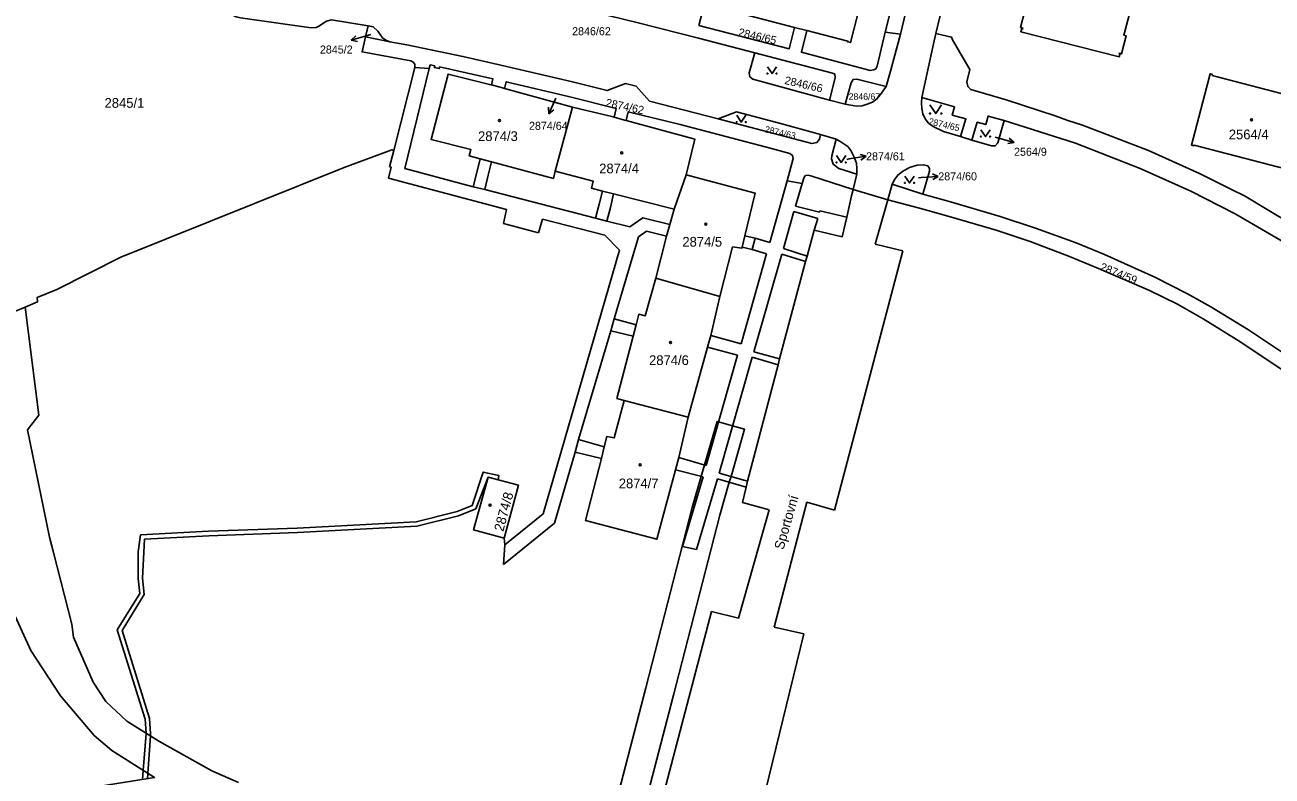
# Model space of a CAD drawing. Extents: x -869103 to -863415, y -1015889 to -1012477.
# Drawn here: x -866820.8 to -866602.7, y -1014847 to -1014715.6 of the extents above; entities that cross this region are included whole.
import ezdxf

# ---------------------------------------------------------------- set-up
doc = ezdxf.new("R2010")
doc.units = 0
for name, color, linetype in [('Hranice parcel', 7, 'Continuous'), ('Parcelní čísla', 7, 'Continuous'), ('Pop  PČ popisy', 7, 'Continuous'), ('Vnitřní kresba', 7, 'Continuous'), ('Věcná břemena k části', 7, 'Continuous'), ('Značky budov', 7, 'Continuous'), ('Značky kultur', 7, 'Continuous')]:
    doc.layers.add(name, color=color, linetype=linetype)

msp = doc.modelspace()

# ---------------------------------------------------------------- linework, layer by layer
at = {"layer": 'Hranice parcel'}
for p, q in [((-866694.25, -1014713.99), (-866686.19, -1014716.05)), ((-866660.75, -1014713.97), (-866661.48, -1014717.12)), ((-866761.23, -1014717.72), (-866760.79, -1014715.79)), ((-866686.19, -1014716.05), (-866684.08, -1014716.59)), ((-866756.99, -1014718.55), (-866761.23, -1014717.72)), ((-866725.06, -1014730), (-866736.96, -1014726.73)), ((-866728.05, -1014741.2), (-866725.06, -1014730)), ((-866677.35, -1014729.5), (-866680.09, -1014728.77)), ((-866681.65, -1014734.8), (-866678.94, -1014735.59)), ((-866655.18, -1014735.77), (-866657.2, -1014735.13)), ((-866707.28, -1014747.85), (-866705.19, -1014741.82)), ((-866675.33, -1014741.7), (-866675.98, -1014744.38)), ((-866675.98, -1014744.38), (-866669.88, -1014746.2)), ((-866669.88, -1014746.2), (-866669.11, -1014743.46)), ((-866663.75, -1014745.2), (-866669.11, -1014743.46)), ((-866710.47, -1014759.93), (-866699.29, -1014763.09)), ((-866716.01, -1014781.3), (-866704.79, -1014784.2))]:
    msp.add_line(p, q, dxfattribs=at)
for points in [[(-866676.2, -1014693.64), (-866667.77, -1014702.31), (-866665.84, -1014706.34), (-866665.79, -1014709.38), (-866667.66, -1014717.25)], [(-866691.76, -1014702.91), (-866691.38, -1014701.47), (-866691, -1014701.57), (-866691.05, -1014701.76), (-866684.3, -1014703.53), (-866682.18, -1014704.08), (-866673.55, -1014706.33), (-866673.5, -1014706.14), (-866673.21, -1014706.17), (-866676.42, -1014718.71), (-866676.9, -1014718.59), (-866676.86, -1014718.44), (-866684.08, -1014716.59)], [(-866693.17, -1014720.49), (-866702.98, -1014717.94), (-866713.55, -1014715.25), (-866726.44, -1014712.08), (-866735.83, -1014709.92), (-866754.2, -1014705.82), (-866768.07, -1014703.14), (-866768.98, -1014707.12), (-866769.32, -1014707.68), (-866769.96, -1014707.85)], [(-866835.15, -1014723.88), (-866828.17, -1014723.42), (-866829.04, -1014715.45), (-866829.11, -1014714.03), (-866828.96, -1014712.67), (-866828.33, -1014711.34), (-866827.39, -1014710.28), (-866826.14, -1014709.44), (-866824.74, -1014708.9), (-866823.27, -1014708.71), (-866814.43, -1014709.34), (-866801.35, -1014710.35), (-866794.57, -1014711), (-866787.9, -1014711.79), (-866784.54, -1014713.88), (-866783.84, -1014714.23), (-866783.1, -1014714.4), (-866770.74, -1014716.15), (-866769.87, -1014716.09), (-866769.4, -1014715.86), (-866768.07, -1014714.98), (-866767.19, -1014714.73), (-866760.79, -1014715.79)], [(-866645.9, -1014712.93), (-866646.71, -1014716.08), (-866646.31, -1014716.17), (-866646.33, -1014716.34), (-866646.48, -1014716.31), (-866646.64, -1014716.81), (-866629.43, -1014721.18), (-866629.3, -1014720.8), (-866629.43, -1014720.75), (-866629.4, -1014720.57), (-866629.03, -1014720.68), (-866628.19, -1014717.5), (-866628.59, -1014717.41), (-866626.69, -1014710.13)], [(-866686.19, -1014716.05), (-866687.16, -1014719.83), (-866702.93, -1014715.72), (-866702.32, -1014713.29)], [(-866760.79, -1014715.79), (-866759.9, -1014715.95), (-866759.11, -1014716.7), (-866758.25, -1014717.89), (-866757.69, -1014718.29), (-866756.99, -1014718.55)], [(-866684.08, -1014716.59), (-866685.01, -1014720.39), (-866672.99, -1014723.57), (-866672.33, -1014723.5), (-866671.97, -1014723.28), (-866671.76, -1014722.83), (-866670.36, -1014716.88), (-866667.66, -1014717.25)], [(-866752.64, -1014723.04), (-866752.62, -1014722.46), (-866752.89, -1014722.13), (-866753.32, -1014721.92), (-866761.83, -1014720.35), (-866761.23, -1014717.72)], [(-866756.99, -1014718.55), (-866754.03, -1014719.11), (-866744.2, -1014721.14), (-866737.58, -1014722.63), (-866725.03, -1014725.6), (-866719, -1014727.11), (-866715.8, -1014725.87), (-866713.9, -1014726.33), (-866711.56, -1014728.97), (-866699.58, -1014732.03)], [(-866667.66, -1014717.25), (-866669.43, -1014723.71), (-866670.21, -1014726.36)], [(-866663.95, -1014728.29), (-866661.9, -1014718.91), (-866661.48, -1014717.12)], [(-866661.48, -1014717.12), (-866658.73, -1014717.76), (-866658.61, -1014718.22), (-866655.54, -1014723.43), (-866656.06, -1014725.6), (-866655.92, -1014726.41), (-866655.35, -1014726.9), (-866649.22, -1014728.72), (-866640.65, -1014731.52), (-866638.41, -1014732.31), (-866635.84, -1014733.17), (-866624.3, -1014737.59), (-866615.38, -1014741.59), (-866609.67, -1014744.44), (-866607.53, -1014745.53), (-866598.99, -1014750.64)], [(-866680.09, -1014728.77), (-866693.48, -1014725.1), (-866694.03, -1014724.68), (-866694.12, -1014724.02), (-866693.17, -1014720.49)], [(-866693.17, -1014720.49), (-866679.57, -1014724.06), (-866679.14, -1014724.24), (-866679.08, -1014724.89), (-866680.09, -1014728.77)], [(-866752.64, -1014723.04), (-866756.29, -1014737.57), (-866756.65, -1014737.49), (-866764.99, -1014740.53), (-866804.04, -1014756.24), (-866815.22, -1014761.87), (-866818.64, -1014763.28), (-866818.58, -1014764.06), (-866820.77, -1014764.96), (-866834.88, -1014770.72)], [(-866739.23, -1014726.12), (-866738.96, -1014725.03), (-866748.29, -1014722.96), (-866748.35, -1014723.26), (-866749.18, -1014723.08), (-866749.12, -1014722.78), (-866749.92, -1014722.6), (-866750.11, -1014723.23), (-866752.64, -1014723.04)], [(-866728.05, -1014741.2), (-866728.38, -1014742.46), (-866739.21, -1014739.58), (-866739.78, -1014741.91), (-866740.39, -1014744.39), (-866742.42, -1014743.91), (-866741.8, -1014741.4), (-866741.18, -1014739.05), (-866743.1, -1014738.54), (-866742.8, -1014737.43), (-866749.76, -1014735.65), (-866746.79, -1014724.26), (-866739.34, -1014726.09), (-866739.23, -1014726.12)], [(-866736.96, -1014726.73), (-866736.64, -1014725.56), (-866725.52, -1014728.21), (-866717.39, -1014730.26), (-866717.78, -1014731.75)], [(-866677.35, -1014729.5), (-866676.3, -1014725.72), (-866675.94, -1014725.14), (-866675.3, -1014725.1), (-866670.21, -1014726.36)], [(-866596, -1014731.53), (-866595.3, -1014728.92), (-866595.69, -1014728.82), (-866595.74, -1014728.99), (-866613.16, -1014724.44), (-866613.12, -1014724.27), (-866613.5, -1014724.16), (-866616.76, -1014736.66), (-866616.37, -1014736.76), (-866616.34, -1014736.64), (-866598.83, -1014741.19), (-866599.21, -1014742.64), (-866598.82, -1014742.75)], [(-866736.96, -1014726.73), (-866737.29, -1014726.64), (-866739.23, -1014726.12)], [(-866670.21, -1014726.36), (-866671.18, -1014727.81), (-866671.82, -1014728.54), (-866672.6, -1014729.1), (-866673.48, -1014729.49), (-866674.41, -1014729.76), (-866675.39, -1014729.81), (-866677.35, -1014729.5)], [(-866717.78, -1014731.75), (-866717.94, -1014731.71), (-866725.06, -1014730)], [(-866657.2, -1014735.13), (-866660.18, -1014734.23), (-866661.98, -1014733.4), (-866662.76, -1014732.78), (-866663.35, -1014732.03), (-866663.77, -1014731.18), (-866663.97, -1014730.25), (-866664.03, -1014729.27), (-866663.95, -1014728.29)], [(-866657.2, -1014735.13), (-866656.25, -1014732.07), (-866658.63, -1014731.41), (-866658.21, -1014729.94), (-866663.95, -1014728.29)], [(-866715.68, -1014732.34), (-866715.94, -1014732.27), (-866717.78, -1014731.75)], [(-866675.98, -1014744.38), (-866683.36, -1014742), (-866683.85, -1014741.89), (-866684.28, -1014741.94), (-866684.55, -1014742.23), (-866684.9, -1014743.32), (-866687.52, -1014742.86), (-866686.45, -1014738.99), (-866686.54, -1014738.44), (-866687.05, -1014738.11), (-866690.24, -1014737.24), (-866706.19, -1014733.06), (-866715.3, -1014730.79), (-866715.68, -1014732.34)], [(-866715.68, -1014732.34), (-866703.66, -1014735.58), (-866705.19, -1014741.82)], [(-866699.58, -1014732.03), (-866696.37, -1014730.83), (-866688.46, -1014732.93), (-866681.65, -1014734.8)], [(-866681.65, -1014734.8), (-866681.84, -1014735.57), (-866682.29, -1014736.2), (-866683.17, -1014736.33), (-866699.58, -1014732.03)], [(-866655.18, -1014735.77), (-866654.24, -1014732.65), (-866652.76, -1014733.04), (-866652.33, -1014731.57), (-866649.56, -1014732.34)], [(-866649.56, -1014732.34), (-866650.65, -1014736.26), (-866651.11, -1014736.76), (-866651.78, -1014736.78), (-866655.18, -1014735.77)], [(-866546.5, -1014803.41), (-866554.27, -1014793.99), (-866562.05, -1014784.82), (-866564.23, -1014782.48), (-866568.35, -1014778.52), (-866571.09, -1014776.01), (-866573.79, -1014779.12), (-866574.41, -1014779.47), (-866575.01, -1014779.24), (-866580.33, -1014774.69), (-866580.61, -1014774.09), (-866580.38, -1014773.5), (-866577.64, -1014770.29), (-866582.87, -1014765.85), (-866588.58, -1014761.57), (-866600.64, -1014753.58), (-866609.13, -1014748.63), (-866616.88, -1014744.71), (-866625.78, -1014740.71), (-866637.08, -1014736.32), (-866649.56, -1014732.34)], [(-866678.94, -1014735.59), (-866679.68, -1014738.49), (-866679.74, -1014739.03), (-866679.43, -1014739.97), (-866678.45, -1014740.7), (-866675.33, -1014741.7)], [(-866678.94, -1014735.59), (-866678.11, -1014736.05), (-866676.9, -1014736.89), (-866676.38, -1014737.59), (-866675.78, -1014738.73), (-866675.4, -1014739.81), (-866675.31, -1014740.73), (-866675.33, -1014741.7)], [(-866669.11, -1014743.46), (-866668.69, -1014742.61), (-866668.15, -1014741.87), (-866667.35, -1014741.25), (-866666.08, -1014740.53), (-866664.78, -1014740.12), (-866663.66, -1014740.1), (-866662.92, -1014740.26), (-866662.59, -1014740.74), (-866662.6, -1014741.19), (-866663.75, -1014745.2)], [(-866707.28, -1014747.85), (-866717.85, -1014745.17), (-866718.38, -1014747.53), (-866719.03, -1014749.94), (-866721.04, -1014749.42), (-866720.39, -1014746.98), (-866719.78, -1014744.68), (-866721.7, -1014744.19), (-866721.44, -1014742.92), (-866728.05, -1014741.2)], [(-866699.29, -1014763.09), (-866697.04, -1014754.43), (-866695.41, -1014754.64), (-866695.37, -1014754.47), (-866693.64, -1014754.91), (-866693.1, -1014752.91), (-866694.88, -1014752.48), (-866693.11, -1014745.01), (-866705.19, -1014741.82)], [(-866663.75, -1014745.2), (-866658.92, -1014746.54), (-866650.22, -1014749.09), (-866644.04, -1014751.13), (-866636.97, -1014753.7), (-866632.02, -1014755.75), (-866623.19, -1014759.72), (-866617.46, -1014762.63), (-866613.41, -1014764.9), (-866606.83, -1014768.94), (-866597.92, -1014774.88), (-866593.48, -1014778.27), (-866588.3, -1014782.62), (-866582.52, -1014787.83)], [(-866591.83, -1014783.07), (-866595.12, -1014780.28), (-866599.53, -1014776.88), (-866608.18, -1014771.11), (-866614.72, -1014767.04), (-866619.23, -1014764.46), (-866624.25, -1014762.01), (-866633.06, -1014758.21), (-866638.12, -1014756.14), (-866644.98, -1014753.48), (-866650.96, -1014751.53), (-866659.56, -1014748.99), (-866664.37, -1014747.65), (-866669.88, -1014746.2)], [(-866707.28, -1014747.85), (-866708.03, -1014750.49), (-866708.6, -1014752.57), (-866710.47, -1014759.93)], [(-866710.47, -1014759.93), (-866712.33, -1014766.5), (-866713.44, -1014766.21), (-866713.93, -1014768.08), (-866717.77, -1014767.03), (-866718.34, -1014769.09), (-866714.44, -1014770.07), (-866717.27, -1014780.97), (-866716.01, -1014781.3)], [(-866704.79, -1014784.2), (-866701.41, -1014771.94), (-866700.87, -1014769.9), (-866699.29, -1014763.09)], [(-866716.01, -1014781.3), (-866717.75, -1014787.83), (-866719.01, -1014787.57), (-866719.48, -1014789.42), (-866723.97, -1014788.12), (-866724.58, -1014790.31), (-866719.99, -1014791.42), (-866722.77, -1014802.26), (-866710.32, -1014805.54), (-866707.02, -1014793.39), (-866706.45, -1014791.28), (-866704.79, -1014784.2)], [(-866734.49, -1014796.11), (-866739.79, -1014794.67), (-866742.33, -1014803.92), (-866736.97, -1014805.36), (-866734.49, -1014796.11)], [(-866827.25, -1014800.81), (-866825.72, -1014805.55), (-866824.43, -1014811.6), (-866822.5, -1014818.99), (-866819.79, -1014824.98), (-866814.59, -1014832.94), (-866808.7, -1014839.84), (-866805.6, -1014842.52), (-866798.13, -1014847.24), (-866829.6, -1014852.2), (-866835.48, -1014853.5), (-866883.36, -1014859.32), (-866885.48, -1014836.57)]]:
    msp.add_lwpolyline(points, dxfattribs=at)
at = {"layer": 'Pop  PČ popisy'}
for p, q in [((-866760.89, -1014717.48), (-866763.78, -1014718.31)), ((-866763.78, -1014718.31), (-866762.95, -1014717.55)), ((-866763.78, -1014718.31), (-866762.67, -1014718.51)), ((-866760.34, -1014717.32), (-866760.89, -1014717.48)), ((-866729.16, -1014731.15), (-866729.21, -1014730.03)), ((-866727.94, -1014728.41), (-866729.16, -1014731.15)), ((-866729.16, -1014731.15), (-866728.3, -1014730.44)), ((-866651.14, -1014735.26), (-866650.71, -1014735.38)), ((-866650.71, -1014735.38), (-866647.81, -1014736.16)), ((-866647.81, -1014736.16), (-866648.91, -1014736.38)), ((-866647.81, -1014736.16), (-866648.65, -1014735.41)), ((-866676.66, -1014739.06), (-866673.7, -1014738.59)), ((-866673.7, -1014738.59), (-866674.76, -1014738.25)), ((-866673.7, -1014738.59), (-866674.61, -1014739.24)), ((-866677.08, -1014739.13), (-866676.66, -1014739.06)), ((-866664.52, -1014742.34), (-866664.06, -1014742.31)), ((-866664.06, -1014742.31), (-866661.07, -1014742.1)), ((-866661.07, -1014742.1), (-866662.1, -1014741.67)), ((-866661.07, -1014742.1), (-866662.03, -1014742.67))]:
    msp.add_line(p, q, dxfattribs=at)
at = {"layer": 'Vnitřní kresba'}
for p, q in [((-866670.36, -1014716.88), (-866668.52, -1014709.63)), ((-866750.11, -1014723.23), (-866754.36, -1014740.72)), ((-866756.29, -1014737.57), (-866757.02, -1014740.42)), ((-866757.25, -1014742.4), (-866756.76, -1014740.49)), ((-866756.76, -1014740.49), (-866757.02, -1014740.42)), ((-866754.36, -1014740.72), (-866742.42, -1014743.91)), ((-866741.18, -1014739.05), (-866739.21, -1014739.58)), ((-866736.58, -1014747.9), (-866757.25, -1014742.4)), ((-866687.52, -1014742.86), (-866690.55, -1014753.65)), ((-866740.39, -1014744.39), (-866721.04, -1014749.42)), ((-866719.78, -1014744.68), (-866717.85, -1014745.17)), ((-866686.03, -1014747.31), (-866684.9, -1014743.32)), ((-866675.98, -1014744.38), (-866676.26, -1014745.52)), ((-866681.87, -1014748.37), (-866686.03, -1014747.31)), ((-866676.26, -1014745.52), (-866677.08, -1014749.21)), ((-866669.88, -1014746.2), (-866672.13, -1014753.98)), ((-866737.13, -1014750.35), (-866736.58, -1014747.9)), ((-866730.29, -1014749.58), (-866730.97, -1014751.98)), ((-866719.39, -1014752.37), (-866730.29, -1014749.58)), ((-866715.04, -1014750.92), (-866712.74, -1014749.34)), ((-866712.74, -1014749.34), (-866708.03, -1014750.49)), ((-866688.14, -1014754.69), (-866686.35, -1014748.27)), ((-866686.35, -1014748.27), (-866682.12, -1014749.47)), ((-866682.12, -1014749.47), (-866682.77, -1014751.53)), ((-866681.87, -1014748.37), (-866681.79, -1014748.12)), ((-866681.79, -1014748.12), (-866677.08, -1014749.21)), ((-866677.08, -1014749.21), (-866677.86, -1014752.66)), ((-866730.97, -1014751.98), (-866737.13, -1014750.35)), ((-866719.03, -1014749.94), (-866715.04, -1014750.92)), ((-866712.08, -1014751.7), (-866713.48, -1014752.67)), ((-866708.6, -1014752.57), (-866712.08, -1014751.7)), ((-866684.01, -1014756.03), (-866682.77, -1014751.53)), ((-866682.77, -1014751.53), (-866677.86, -1014752.66)), ((-866719.39, -1014752.37), (-866716.8, -1014755.02)), ((-866713.48, -1014752.67), (-866717.77, -1014767.03)), ((-866694.88, -1014752.48), (-866695.37, -1014754.47)), ((-866693.1, -1014752.91), (-866690.55, -1014753.65)), ((-866672.13, -1014753.98), (-866667.25, -1014755.14)), ((-866716.8, -1014755.02), (-866730.18, -1014801.12)), ((-866691.12, -1014755.63), (-866695.56, -1014771.37)), ((-866693.64, -1014754.91), (-866691.12, -1014755.63)), ((-866693.35, -1014772.76), (-866688.41, -1014755.68)), ((-866688.41, -1014755.68), (-866684.28, -1014756.98)), ((-866684.01, -1014756.03), (-866688.14, -1014754.69)), ((-866684.01, -1014756.03), (-866684.28, -1014756.98)), ((-866667.25, -1014755.14), (-866679.23, -1014800.45)), ((-866684.28, -1014756.98), (-866688.84, -1014774.02)), ((-866818.36, -1014783.85), (-866820.77, -1014764.96)), ((-866723.97, -1014788.12), (-866718.34, -1014769.09)), ((-866714.44, -1014770.07), (-866713.93, -1014768.08)), ((-866695.56, -1014771.37), (-866700.87, -1014769.9)), ((-866701.67, -1014792.64), (-866696.19, -1014773.39)), ((-866701.41, -1014771.94), (-866696.19, -1014773.39)), ((-866699.41, -1014793.97), (-866693.63, -1014773.74)), ((-866693.63, -1014773.74), (-866689.08, -1014775.05)), ((-866688.84, -1014774.02), (-866693.35, -1014772.76)), ((-866689.08, -1014775.05), (-866694.43, -1014795.39)), ((-866688.84, -1014774.02), (-866689.08, -1014775.05)), ((-866820.37, -1014786.42), (-866818.36, -1014783.85)), ((-866816.52, -1014805.21), (-866820.37, -1014786.42)), ((-866728.17, -1014802.73), (-866724.58, -1014790.31)), ((-866719.99, -1014791.42), (-866719.48, -1014789.42)), ((-866707.02, -1014793.39), (-866702.18, -1014794.65)), ((-866701.67, -1014792.64), (-866706.45, -1014791.28)), ((-866702.18, -1014794.65), (-866705.82, -1014806.84)), ((-866703.35, -1014807.34), (-866699.7, -1014795)), ((-866699.7, -1014795), (-866694.67, -1014796.45)), ((-866699.41, -1014793.97), (-866694.43, -1014795.39)), ((-866694.43, -1014795.39), (-866694.67, -1014796.45)), ((-866694.67, -1014796.45), (-866695.29, -1014799.11)), ((-866695.29, -1014799.11), (-866690.66, -1014800.39)), ((-866689.77, -1014820.9), (-866684.03, -1014799.09)), ((-866684.03, -1014799.09), (-866679.23, -1014800.45)), ((-866730.18, -1014801.12), (-866736.86, -1014806.51)), ((-866690.66, -1014800.39), (-866695.99, -1014819.37)), ((-866737.13, -1014809.98), (-866728.17, -1014802.73)), ((-866815.82, -1014807.86), (-866816.52, -1014805.21)), ((-866736.97, -1014805.36), (-866736.86, -1014806.51)), ((-866812.62, -1014820.4), (-866815.82, -1014807.86)), ((-866736.86, -1014806.51), (-866737.13, -1014809.98)), ((-866705.82, -1014806.84), (-866703.35, -1014807.34)), ((-866700.75, -1014818.2), (-866710.15, -1014853.94)), ((-866695.99, -1014819.37), (-866700.75, -1014818.2)), ((-866812.3, -1014822.68), (-866812.62, -1014820.4)), ((-866684.57, -1014822.08), (-866689.77, -1014820.9)), ((-866808.86, -1014830.55), (-866812.3, -1014822.68)), ((-866693.49, -1014858.4), (-866684.57, -1014822.08)), ((-866806.66, -1014833.93), (-866808.86, -1014830.55)), ((-866802.98, -1014837.36), (-866806.66, -1014833.93)), ((-866797.4, -1014840.84), (-866802.98, -1014837.36)), ((-866788.1, -1014846.05), (-866797.4, -1014840.84)), ((-866783.43, -1014848.1), (-866788.1, -1014846.05))]:
    msp.add_line(p, q, dxfattribs=at)
at = {"layer": 'Věcná břemena k části'}
for points in [[(-866712.52, -1014852.52), (-866707.38, -1014832.81), (-866699.26, -1014801.34), (-866697.62, -1014795.6), (-866697.32, -1014794.57), (-866694.96, -1014786.32), (-866697.05, -1014785.72), (-866699.5, -1014785.01), (-866699.76, -1014784.94), (-866701.95, -1014792.56), (-866702.52, -1014794.56), (-866704.09, -1014800.02), (-866712.22, -1014831.55), (-866717.37, -1014851.29)], [(-866799.35, -1014847.43), (-866799.29, -1014846.51), (-866798.86, -1014839.93), (-866798.83, -1014839.52), (-866799.04, -1014836.88), (-866803.83, -1014821.52), (-866799.95, -1014815.23), (-866800.26, -1014812.36), (-866799.91, -1014805.54), (-866788.67, -1014804.93), (-866773.14, -1014804.38), (-866752.25, -1014803.27), (-866744.99, -1014801.43), (-866741.96, -1014800.22), (-866739.79, -1014794.67), (-866738.06, -1014795.14), (-866737.9, -1014794.41), (-866740.64, -1014793.81), (-866742.57, -1014799.63), (-866745.23, -1014800.69), (-866752.37, -1014802.5), (-866773.17, -1014803.61), (-866788.7, -1014804.16), (-866800.58, -1014804.8), (-866800.99, -1014807.77), (-866801.03, -1014812.4), (-866800.74, -1014815.05), (-866804.67, -1014821.42), (-866799.8, -1014837.03), (-866799.6, -1014839.47), (-866799.6, -1014839.52), (-866800.1, -1014845.99), (-866800.22, -1014847.57)]]:
    msp.add_lwpolyline(points, dxfattribs=at)
at = {"layer": 'Značky budov'}
for centre in [(-866737.81, -1014732.34), (-866606.27, -1014732.2), (-866716.44, -1014737.98), (-866701.74, -1014750.47), (-866707.9, -1014771.16), (-866713.2, -1014792.54), (-866739.47, -1014799.59)]:
    msp.add_circle(centre, 0.175, dxfattribs=at)
at = {"layer": 'Značky kultur'}
for points in [[(-866690.95, -1014722.94), (-866690.15, -1014724.14), (-866689.35, -1014722.94)], [(-866662.52, -1014729.61), (-866661.52, -1014731.11), (-866660.52, -1014729.61)], [(-866696.33, -1014731.41), (-866695.53, -1014732.61), (-866694.73, -1014731.41)], [(-866653.61, -1014733.94), (-866652.81, -1014735.14), (-866652.01, -1014733.94)], [(-866678.86, -1014738.47), (-866678.06, -1014739.67), (-866677.26, -1014738.47)], [(-866666.9, -1014742.04), (-866666.1, -1014743.24), (-866665.3, -1014742.04)]]:
    msp.add_lwpolyline(points, dxfattribs=at)
for centre, radius in [((-866690.95, -1014724.14), 0.08), ((-866689.35, -1014724.14), 0.08), ((-866662.52, -1014731.11), 0.1), ((-866660.52, -1014731.11), 0.1), ((-866696.33, -1014732.61), 0.08), ((-866694.73, -1014732.61), 0.08), ((-866653.61, -1014735.14), 0.08), ((-866652.01, -1014735.14), 0.08), ((-866678.86, -1014739.67), 0.08), ((-866677.26, -1014739.67), 0.08), ((-866666.9, -1014743.24), 0.08), ((-866665.3, -1014743.24), 0.08)]:
    msp.add_circle(centre, radius, dxfattribs=at)

# ---------------------------------------------------------------- texts
at = {"layer": 'Parcelní čísla'}
for s, height, p in [('2846/62', 1.4, (-866725.11, -1014717.42)), ('2845/2', 1.4, (-866769.22, -1014720.62)), ('2846/67', 1.139, (-866676.74, -1014728.71)), ('2845/1', 1.7, (-866806.88, -1014730.11)), ('2874/3', 1.7, (-866741.56, -1014735.92)), ('2874/64', 1.4, (-866732.65, -1014733.96)), ('2564/4', 1.7, (-866610.26, -1014735.62)), ('2874/61', 1.4, (-866673.7, -1014739.29)), ('2564/9', 1.4, (-866647.82, -1014738.5)), ('2874/4', 1.7, (-866720.37, -1014741.57)), ('2874/60', 1.4, (-866661.07, -1014742.79)), ('2874/5', 1.7, (-866705.83, -1014754.39)), ('2874/6', 1.7, (-866711.65, -1014775.09)), ('2874/7', 1.7, (-866716.95, -1014796.64))]:
    msp.add_text(s, height=height, dxfattribs=at).set_placement(p)
for s, height, rotation, p in [('2846/65', 1.4, 347, (-866696.15, -1014717.52)), ('2846/66', 1.4, 347, (-866688.05, -1014725.93)), ('2874/62', 1.4, 348, (-866719.33, -1014729.85)), ('2874/65', 1.139, 347, (-866662.85, -1014732.99)), ('2874/63', 1.139, 347, (-866691.51, -1014734.37)), ('2874/59', 1.4, 338, (-866632.91, -1014758.45)), ('2874/8', 1.7, 75, (-866737.15, -1014804.3))]:
    msp.add_text(s, height=height, rotation=rotation, dxfattribs=at).set_placement(p)
at = {"layer": 'Pop  PČ popisy'}
msp.add_text('Sportovní', height=1.7, rotation=74, dxfattribs=at).set_placement((-866688.16, -1014807.5))

doc.saveas('drawing.dxf')
